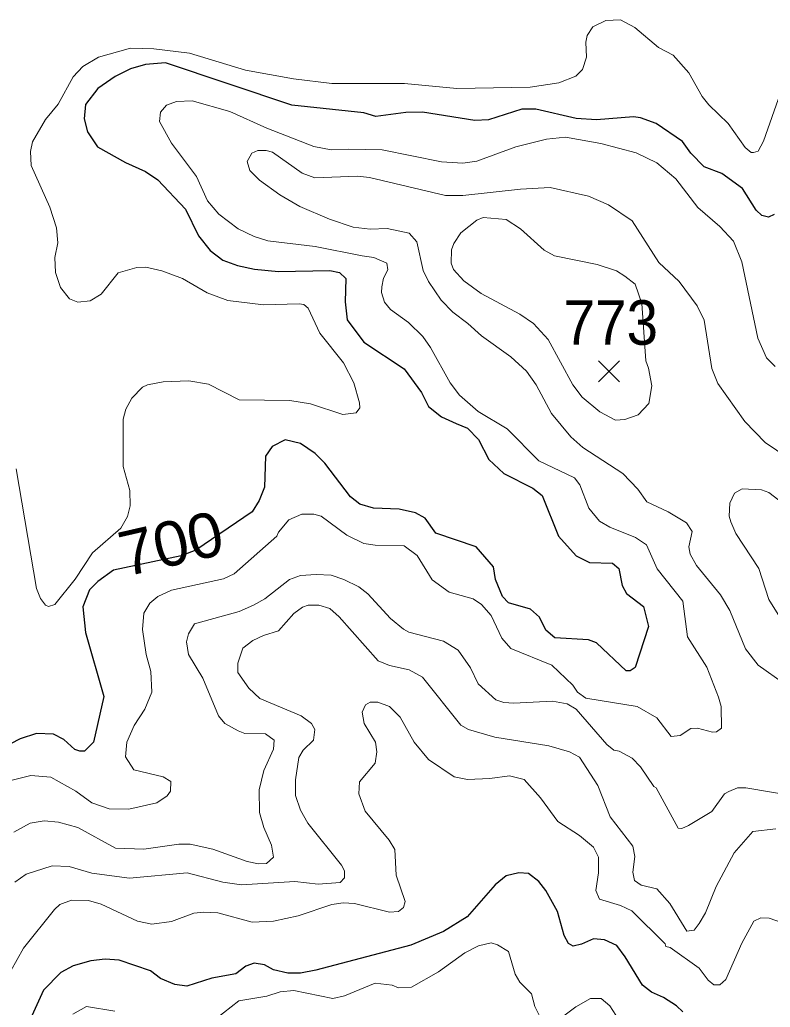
# Model space of a CAD drawing. Extents: x 294.2 to 320.3, y 7482.7 to 7510.7.
# Drawn here: x 315.382 to 316.729, y 7484.568 to 7486.341 of the extents above; entities that cross this region are included whole.
import ezdxf
from ezdxf.enums import TextEntityAlignment as Align

# ---------------------------------------------------------------- set-up
doc = ezdxf.new("R2010")
doc.units = 0
doc.header["$LTSCALE"] = 0.032
for name, color, linetype, lineweight in [('1', 7, 'Continuous', 25), ('2', 7, 'Continuous', 13), ('21', 7, 'Continuous', 25)]:
    doc.layers.add(name, color=color, linetype=linetype, lineweight=lineweight)
doc.layers.add('61', color=7, linetype='Continuous')

msp = doc.modelspace()

# ---------------------------------------------------------------- linework, layer by layer
at = {"layer": '1'}
for points in [[(315.5807, 7486.2529), (315.5535, 7486.2394), (315.5225, 7486.2179), (315.5003, 7486.1889), (315.4975, 7486.1636), (315.5036, 7486.1399), (315.5219, 7486.113), (315.5718, 7486.0851), (315.6078, 7486.069), (315.63, 7486.0539), (315.6799, 7486.0012), (315.7027, 7485.9533), (315.7237, 7485.927), (315.7465, 7485.9098), (315.7731, 7485.9001), (315.8036, 7485.8936), (315.8468, 7485.8893), (315.9389, 7485.8909), (315.9561, 7485.8872), (315.9672, 7485.8764), (315.9661, 7485.835), (315.97, 7485.8027), (315.9999, 7485.7624), (316.072, 7485.7145), (316.1031, 7485.672), (316.1158, 7485.6467), (316.1391, 7485.6284), (316.1652, 7485.6166), (316.186, 7485.6079), (316.2052, 7485.5877), (316.224, 7485.5515), (316.2512, 7485.5268), (316.3028, 7485.5005), (316.32, 7485.487), (316.3488, 7485.4139), (316.381, 7485.3789), (316.4048, 7485.3666), (316.4459, 7485.3655), (316.4575, 7485.3558), (316.4636, 7485.3257), (316.4708, 7485.3112), (316.5013, 7485.2875), (316.5107, 7485.252), (316.4868, 7485.1783), (316.4774, 7485.1724), (316.4702, 7485.1724), (316.417, 7485.2224), (316.4031, 7485.2278), (316.3427, 7485.2316), (316.3266, 7485.245), (316.315, 7485.2687), (316.2989, 7485.2827), (316.2595, 7485.2945), (316.2484, 7485.3058), (316.2362, 7485.3365), (316.2324, 7485.3591), (316.2013, 7485.3951), (316.1292, 7485.4193), (316.1098, 7485.4462), (316.0926, 7485.4559), (316.0634, 7485.4624), (316.0172, 7485.4645), (315.9927, 7485.4715), (315.9755, 7485.4844), (315.9295, 7485.5453), (315.9123, 7485.5625), (315.8862, 7485.5807), (315.8584, 7485.5872), (315.8351, 7485.5748), (315.8233, 7485.5574), (315.8213, 7485.5022), (315.8119, 7485.4779), (315.7991, 7485.4575), (315.6981, 7485.3887), (315.672, 7485.379), (315.5505, 7485.3532), (315.5222, 7485.3327), (315.5073, 7485.3177), (315.4952, 7485.2871), (315.5003, 7485.2411), (315.5328, 7485.1262), (315.5143, 7485.0445), (315.4983, 7485.0279), (315.4901, 7485.0279), (315.4811, 7485.0311), (315.4613, 7485.049), (315.4428, 7485.0585), (315.4122, 7485.0598), (315.3828, 7485.0502), (315.3103, 7485.0129)], [(316.0749, 7486.1746), (316.021, 7486.1674), (315.9994, 7486.1739), (315.8702, 7486.1879), (315.6439, 7486.2637), (315.6079, 7486.261), (315.5807, 7486.2529)], [(316.7362, 7485.9917), (316.7262, 7485.9869), (316.714, 7485.9896), (316.7035, 7485.9993), (316.679, 7486.038), (316.6419, 7486.0654), (316.6106, 7486.0769), (316.5863, 7486.1018), (316.5716, 7486.1229), (316.5244, 7486.1548), (316.4963, 7486.165), (316.4835, 7486.1669), (316.4173, 7486.1613), (316.3807, 7486.164), (316.3085, 7486.1806), (316.283, 7486.1806), (316.2236, 7486.1618), (316.1987, 7486.1602), (316.1049, 7486.1752), (316.0749, 7486.1746)], [(316.5719, 7484.5603), (316.5608, 7484.5711), (316.5375, 7484.5861), (316.5159, 7484.5953), (316.4998, 7484.6082), (316.4687, 7484.6588), (316.4538, 7484.6793), (316.4316, 7484.6895), (316.4116, 7484.6911), (316.3905, 7484.6814), (316.3756, 7484.6782), (316.3667, 7484.683), (316.3595, 7484.697), (316.3473, 7484.74), (316.3262, 7484.7777), (316.314, 7484.7938), (316.2951, 7484.8083), (316.2779, 7484.8099), (316.2552, 7484.804), (316.2352, 7484.7879), (316.1853, 7484.7309), (316.1426, 7484.704), (316.0838, 7484.6798), (315.9136, 7484.6348), (315.8858, 7484.6294), (315.8631, 7484.6294), (315.8376, 7484.6353), (315.8215, 7484.6445), (315.8027, 7484.6477), (315.7877, 7484.6423), (315.77, 7484.6283), (315.7267, 7484.6207), (315.6823, 7484.6062), (315.6607, 7484.6094), (315.6346, 7484.6202), (315.6169, 7484.6337), (315.5604, 7484.6531), (315.5354, 7484.6547), (315.5099, 7484.6515), (315.4783, 7484.6424), (315.4561, 7484.6305), (315.4251, 7484.5988), (315.4007, 7484.5466)]]:
    msp.add_lwpolyline(points, dxfattribs=at)
at = {"layer": '2'}
for points in [[(315.3758, 7485.5348), (315.4121, 7485.3203), (315.4192, 7485.3024), (315.4281, 7485.2903), (315.4339, 7485.2877), (315.4454, 7485.2916), (315.4818, 7485.3369), (315.513, 7485.3841), (315.5635, 7485.4282), (315.5756, 7485.4493), (315.5801, 7485.4684), (315.58, 7485.4958), (315.568, 7485.5392), (315.5679, 7485.6242), (315.5724, 7485.6421), (315.5832, 7485.6619), (315.6024, 7485.6817), (315.6114, 7485.6855), (315.6395, 7485.6913), (315.6854, 7485.6931), (315.7212, 7485.6868), (315.7761, 7485.6587), (315.8668, 7485.6574), (315.9038, 7485.6517), (315.9619, 7485.6325), (315.9862, 7485.6357), (315.9925, 7485.6447), (315.9919, 7485.6536), (315.9817, 7485.6894), (315.9632, 7485.7251), (315.921, 7485.7787), (315.9, 7485.8234), (315.8923, 7485.8298), (315.8834, 7485.8311), (315.8195, 7485.8292), (315.7557, 7485.8374), (315.7186, 7485.8509), (315.674, 7485.8764), (315.6369, 7485.8905), (315.6082, 7485.8969), (315.5922, 7485.8962), (315.559, 7485.8866), (315.5284, 7485.8483), (315.5086, 7485.8368), (315.4862, 7485.8343), (315.4716, 7485.84), (315.4556, 7485.8605), (315.4466, 7485.8873), (315.4453, 7485.9141), (315.4504, 7485.9409), (315.4479, 7485.9677), (315.4364, 7486.0048), (315.4026, 7486.0795), (315.4013, 7486.1044), (315.4051, 7486.1222), (315.4281, 7486.1624), (315.4511, 7486.1899), (315.4779, 7486.2389), (315.4952, 7486.2573), (315.5236, 7486.274), (315.5807, 7486.2902), (315.6229, 7486.2889), (315.6867, 7486.2812), (315.7876, 7486.2506), (315.8732, 7486.2352), (315.9421, 7486.2269), (316.0724, 7486.2269), (316.1666, 7486.2178), (316.2984, 7486.2199), (316.3495, 7486.2282), (316.3801, 7486.2397), (316.3922, 7486.2518), (316.3992, 7486.2742), (316.3979, 7486.301), (316.4005, 7486.3131), (316.4107, 7486.3285), (316.4337, 7486.34), (316.4606, 7486.3412), (316.4861, 7486.3272), (316.5288, 7486.2914), (316.555, 7486.2774), (316.5831, 7486.2461), (316.6068, 7486.2033), (316.6186, 7486.1885), (316.6536, 7486.155), (316.684, 7486.112), (316.6948, 7486.103), (316.6993, 7486.103), (316.7076, 7486.105), (316.7172, 7486.1235)], [(316.7172, 7486.1235), (316.7472, 7486.2097), (316.767, 7486.2301), (316.7977, 7486.2422), (316.804, 7486.2512), (316.8053, 7486.2614), (316.7951, 7486.3125)], [(316.7377, 7485.7187), (316.7223, 7485.7341), (316.707, 7485.7698), (316.6783, 7485.9064), (316.6629, 7485.9435), (316.6387, 7485.9703), (316.5991, 7486.0041), (316.5595, 7486.0558), (316.5257, 7486.0846), (316.4887, 7486.1024), (316.4248, 7486.119), (316.3616, 7486.1305), (316.3278, 7486.1267), (316.2726, 7486.1131), (316.2025, 7486.0873), (316.1773, 7486.0839), (316.1388, 7486.0861), (316.0328, 7486.1076), (315.9715, 7486.1088), (315.9408, 7486.1076), (315.9102, 7486.1139), (315.8259, 7486.1465), (315.7595, 7486.1765), (315.6918, 7486.1957), (315.6637, 7486.1944), (315.6458, 7486.188), (315.635, 7486.1752), (315.633, 7486.1586), (315.6548, 7486.1197), (315.6994, 7486.0597), (315.7193, 7486.0163), (315.7397, 7485.9919), (315.7742, 7485.9658), (315.8029, 7485.9518), (315.8272, 7485.9441), (315.9122, 7485.9344), (315.997, 7485.9173), (316.0175, 7485.9141), (316.0411, 7485.9039), (316.043, 7485.8924), (316.0347, 7485.8771), (316.0321, 7485.8617), (316.0315, 7485.8515), (316.0366, 7485.8343), (316.0474, 7485.8208), (316.0796, 7485.7979), (316.1055, 7485.7723), (316.1196, 7485.7525), (316.1547, 7485.6894), (316.1713, 7485.667), (316.2051, 7485.6376), (316.2568, 7485.607)], [(316.7548, 7485.1487), (316.7071, 7485.1826), (316.6847, 7485.2118), (316.6566, 7485.2807), (316.6399, 7485.3088), (316.5965, 7485.3612), (316.5851, 7485.3816), (316.5831, 7485.395), (316.5889, 7485.4225), (316.5787, 7485.4378), (316.5461, 7485.4576), (316.5078, 7485.4755), (316.4912, 7485.4984), (316.4644, 7485.5265), (316.3929, 7485.5731), (316.3711, 7485.5923), (316.3367, 7485.6344), (316.3092, 7485.6855), (316.2914, 7485.7104), (316.2633, 7485.736), (316.2109, 7485.7736), (316.1866, 7485.7959), (316.1592, 7485.8164), (316.1387, 7485.8375), (316.1158, 7485.8713), (316.1062, 7485.8911), (316.0947, 7485.9422), (316.0813, 7485.9581), (316.0417, 7485.9664), (316.0111, 7485.9651), (315.9804, 7485.969), (315.9383, 7485.983), (315.8847, 7486.006), (315.8489, 7486.0271), (315.8125, 7486.0532), (315.7952, 7486.0705), (315.7901, 7486.0865), (315.7984, 7486.1018), (315.8093, 7486.1063), (315.8246, 7486.1063), (315.8355, 7486.1037), (315.8891, 7486.066), (315.9115, 7486.0571), (315.9881, 7486.0603), (316.0098, 7486.0578), (316.1464, 7486.0258), (316.1771, 7486.0258), (316.2811, 7486.0373), (316.3341, 7486.0399), (316.4031, 7486.0245), (316.4389, 7486.0092), (316.481, 7485.9799), (316.5289, 7485.9051), (316.5659, 7485.8713), (316.5978, 7485.8273), (316.6106, 7485.8017), (316.624, 7485.7149), (316.6349, 7485.6881), (316.6834, 7485.6197), (316.7197, 7485.5821), (316.7606, 7485.5546)], [(316.2568, 7485.607), (316.3137, 7485.5495), (316.3776, 7485.5189), (316.3871, 7485.5061), (316.4037, 7485.4646), (316.4229, 7485.441), (316.4414, 7485.4301)], [(316.7676, 7485.4608), (316.7268, 7485.4927), (316.7134, 7485.4972), (316.6789, 7485.4991), (316.6648, 7485.4914), (316.6566, 7485.4736), (316.6553, 7485.4499), (316.6584, 7485.4397), (316.6674, 7485.4186), (316.7083, 7485.3561), (316.7266, 7485.3006), (316.7461, 7485.2688)], [(316.4414, 7485.4301), (316.4874, 7485.4116), (316.5071, 7485.3982), (316.5263, 7485.3554), (316.5722, 7485.2973), (316.5806, 7485.2335), (316.615, 7485.1786), (316.6361, 7485.1249), (316.6412, 7485.1083), (316.6418, 7485.0694), (316.6329, 7485.063), (316.6253, 7485.0623), (316.5985, 7485.0694), (316.5863, 7485.0687), (316.5671, 7485.056), (316.5512, 7485.0541), (316.5257, 7485.0879), (316.4905, 7485.1083), (316.3979, 7485.123), (316.3833, 7485.1339), (316.375, 7485.1466), (316.3373, 7485.1824), (316.2633, 7485.2124), (316.2473, 7485.2309), (316.2281, 7485.2718), (316.2109, 7485.2915), (316.1962, 7485.3018), (316.1528, 7485.3133), (316.1221, 7485.3356), (316.0953, 7485.3791), (316.0723, 7485.3969), (316.02, 7485.3976), (315.9996, 7485.4007), (315.9689, 7485.416), (315.9229, 7485.4499), (315.9102, 7485.4538), (315.8885, 7485.4538), (315.8648, 7485.4435), (315.8463, 7485.4212), (315.8438, 7485.4142), (315.7672, 7485.3465), (315.748, 7485.3375), (315.6548, 7485.3171), (315.6299, 7485.3056), (315.6158, 7485.2935), (315.605, 7485.2756), (315.6024, 7485.2463), (315.6088, 7485.2016), (315.6177, 7485.1709), (315.619, 7485.1339), (315.6069, 7485.1032), (315.5878, 7485.0739), (315.5743, 7485.0445), (315.5718, 7485.0177), (315.5871, 7484.9946), (315.6395, 7484.9819), (315.6535, 7484.9736), (315.6529, 7484.9564), (315.6465, 7484.948), (315.628, 7484.9353), (315.5782, 7484.9238), (315.5424, 7484.9244), (315.5118, 7484.9353), (315.483, 7484.9563), (315.4377, 7484.9813), (315.402, 7484.9844), (315.3611, 7484.9742)], [(315.3713, 7484.8829), (315.4007, 7484.8989), (315.4262, 7484.9027), (315.4518, 7484.9008), (315.4862, 7484.8912), (315.5539, 7484.8542), (315.605, 7484.8523), (315.6676, 7484.8612), (315.688, 7484.8612), (315.7289, 7484.8523), (315.7902, 7484.8299), (315.8106, 7484.8255), (315.8252, 7484.8261), (315.8374, 7484.8376), (315.8342, 7484.8593), (315.8202, 7484.8913), (315.8125, 7484.918), (315.8118, 7484.9589), (315.8202, 7484.9934), (315.8374, 7485.0317), (315.8386, 7485.0476), (315.8233, 7485.0592), (315.7863, 7485.0598), (315.7742, 7485.0643), (315.7505, 7485.0777), (315.739, 7485.0917), (315.711, 7485.1594), (315.6848, 7485.2016), (315.6816, 7485.2245), (315.6848, 7485.2386), (315.6956, 7485.2564), (315.7761, 7485.2788), (315.8017, 7485.2903), (315.8221, 7485.3018), (315.8661, 7485.3363), (315.8859, 7485.3433), (315.914, 7485.3452), (315.9408, 7485.3439), (315.9638, 7485.3363), (315.9906, 7485.3228), (316.0066, 7485.3107), (316.0474, 7485.266), (316.0711, 7485.2469), (316.0806, 7485.2418), (316.1426, 7485.2258), (316.1688, 7485.2092), (316.1911, 7485.1779), (316.2051, 7485.1492), (316.2364, 7485.1205), (316.2511, 7485.1154), (316.269, 7485.1141), (316.338, 7485.1179), (316.3648, 7485.1128), (316.3807, 7485.1032), (316.4356, 7485.04), (316.4484, 7485.0298), (316.458, 7485.0279), (316.481, 7485.0157), (316.4963, 7484.9998)], [(316.7389, 7484.8887), (316.698, 7484.8836), (316.6642, 7484.8453), (316.6323, 7484.7853), (316.6131, 7484.738), (316.6017, 7484.7189), (316.5927, 7484.7067), (316.5793, 7484.7048), (316.5486, 7484.7546), (316.5257, 7484.7808), (316.4976, 7484.7872), (316.4854, 7484.7961), (316.4822, 7484.8108), (316.4861, 7484.8389), (316.4822, 7484.8574), (316.442, 7484.9104), (316.4196, 7484.9666), (316.3865, 7485.017), (316.3686, 7485.0266), (316.3316, 7485.0375), (316.2345, 7485.0534), (316.1873, 7485.0668), (316.1739, 7485.0745), (316.1049, 7485.1607), (316.0813, 7485.1741), (316.0455, 7485.1818), (316.0257, 7485.19), (315.9555, 7485.2692), (315.9389, 7485.2839), (315.9191, 7485.2903), (315.9, 7485.2903), (315.8898, 7485.2865), (315.8738, 7485.275), (315.8463, 7485.2443), (315.8195, 7485.236), (315.8004, 7485.2265), (315.7825, 7485.213), (315.7735, 7485.1862), (315.7736, 7485.1692), (315.7931, 7485.1413), (315.8132, 7485.1224), (315.8873, 7485.0914), (315.9057, 7485.0775), (315.912, 7485.0669), (315.9091, 7485.0479), (315.891, 7485.0298), (315.8833, 7485.0164), (315.8769, 7484.9768), (315.8769, 7484.9487), (315.8859, 7484.9219), (315.8993, 7484.8989), (315.9599, 7484.8236), (315.9651, 7484.8134), (315.9651, 7484.8006), (315.9574, 7484.7923), (315.9179, 7484.7891), (315.8757, 7484.7942), (315.7799, 7484.7878), (315.7467, 7484.7929), (315.6829, 7484.8095), (315.5793, 7484.8001), (315.5118, 7484.8089), (315.4709, 7484.821), (315.4403, 7484.8223), (315.3936, 7484.807), (315.3732, 7484.7929)], [(315.366, 7484.6338), (315.3892, 7484.6742), (315.4447, 7484.7438), (315.4543, 7484.7527), (315.4748, 7484.7604), (315.5054, 7484.7597), (315.5284, 7484.7533), (315.5935, 7484.7227), (315.619, 7484.7175), (315.6548, 7484.7221), (315.6944, 7484.7374), (315.7123, 7484.7393), (315.7378, 7484.738), (315.7991, 7484.7208), (315.8374, 7484.7227), (315.8821, 7484.7323), (315.9421, 7484.7527), (315.9625, 7484.7559), (315.983, 7484.7546), (316.0455, 7484.7393), (316.0621, 7484.7405), (316.0711, 7484.7476), (316.0736, 7484.7584), (316.0577, 7484.8057), (316.0551, 7484.8517), (316.0449, 7484.8683), (316.0021, 7484.9206), (315.9906, 7484.9513), (315.9919, 7484.973), (316.02, 7485.0068), (316.0232, 7485.0266), (316.0206, 7485.0445), (316.0002, 7485.0777), (315.997, 7485.0981), (316.0028, 7485.1115), (316.011, 7485.116), (316.0251, 7485.116), (316.0455, 7485.1083), (316.0647, 7485.0892), (316.0902, 7485.0445), (316.1158, 7485.0132), (316.1617, 7484.9819), (316.186, 7484.9774), (316.2256, 7484.9787), (316.2614, 7484.9838), (316.2875, 7484.9774), (316.3169, 7484.9442), (316.3481, 7484.9015), (316.3865, 7484.8766), (316.412, 7484.8555), (316.4209, 7484.8376), (316.4209, 7484.8095), (316.4158, 7484.7778), (316.4226, 7484.7622), (316.4605, 7484.7511), (316.4806, 7484.7416), (316.5403, 7484.6824), (316.5416, 7484.6774), (316.5493, 7484.6754), (316.6016, 7484.6384), (316.6176, 7484.6167), (316.6278, 7484.6084), (316.6387, 7484.6084), (316.6495, 7484.6179), (316.6783, 7484.6834), (316.6996, 7484.723), (316.7122, 7484.7291), (316.7271, 7484.7285), (316.753, 7484.7191)], [(316.4963, 7484.9998), (316.5199, 7484.9647), (316.5244, 7484.9621), (316.564, 7484.8899), (316.5704, 7484.8893), (316.5825, 7484.8944), (316.624, 7484.92)], [(316.624, 7484.92), (316.6469, 7484.9513), (316.6547, 7484.9557), (316.67, 7484.9621), (316.6853, 7484.9621), (316.7772, 7484.9468)], [(316.3163, 7484.5503), (316.3067, 7484.5695), (316.3003, 7484.5925), (316.2799, 7484.6135), (316.2715, 7484.6275), (316.2594, 7484.6684), (316.2396, 7484.6805), (316.2282, 7484.6837), (316.2052, 7484.6786), (316.1809, 7484.6659), (316.1337, 7484.632), (316.0851, 7484.6046), (316.0621, 7484.6033), (316.0507, 7484.6077), (316.0201, 7484.6117), (315.965, 7484.5889), (315.9443, 7484.5839), (315.8743, 7484.5981), (315.8497, 7484.5958), (315.8255, 7484.588), (315.7756, 7484.5799), (315.734, 7484.5477)], [(316.4522, 7484.5541), (316.4414, 7484.5707), (316.4254, 7484.5841), (316.4062, 7484.5841), (316.3801, 7484.5688), (316.3584, 7484.5528)], [(315.5526, 7484.5612), (315.5022, 7484.5694), (315.4773, 7484.5561)]]:
    msp.add_lwpolyline(points, dxfattribs=at)
msp.add_lwpolyline([(316.4682, 7485.6235), (316.4516, 7485.6223), (316.4235, 7485.637), (316.3916, 7485.6638), (316.375, 7485.6855), (316.3303, 7485.7673), (316.3041, 7485.796), (316.2798, 7485.8126), (316.2103, 7485.8496), (316.179, 7485.8726), (316.1604, 7485.893), (316.1566, 7485.9039), (316.1573, 7485.9281), (316.1611, 7485.9396), (316.1738, 7485.9587), (316.2026, 7485.9811), (316.2141, 7485.9862), (316.255, 7485.9824), (316.2811, 7485.9658), (316.3232, 7485.9275), (316.3418, 7485.9173), (316.4184, 7485.902), (316.4529, 7485.8905), (316.4682, 7485.8809), (316.4867, 7485.8662), (316.4989, 7485.8317), (316.5055, 7485.7289), (316.5105, 7485.7155), (316.5167, 7485.6842), (316.511, 7485.6523), (316.4918, 7485.6318)], close=True, dxfattribs=at)
at = {"layer": '21'}
for p, q in [((316.4208, 7485.7289), (316.4583, 7485.6914)), ((316.4583, 7485.7289), (316.4208, 7485.6914))]:
    msp.add_line(p, q, dxfattribs=at)

# ---------------------------------------------------------------- texts
at = {"layer": '61', "width": 0.95}
msp.add_text('773', height=0.08, dxfattribs=at).set_placement((316.4429, 7485.7577), align=Align.CENTER)
at = {"layer": '61', "width": 1.05}
msp.add_text('700', height=0.08, rotation=12.908, dxfattribs=at).set_placement((315.6624, 7485.362), align=Align.CENTER)

doc.saveas('drawing.dxf')
